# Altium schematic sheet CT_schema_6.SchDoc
size 278 x 170 mm
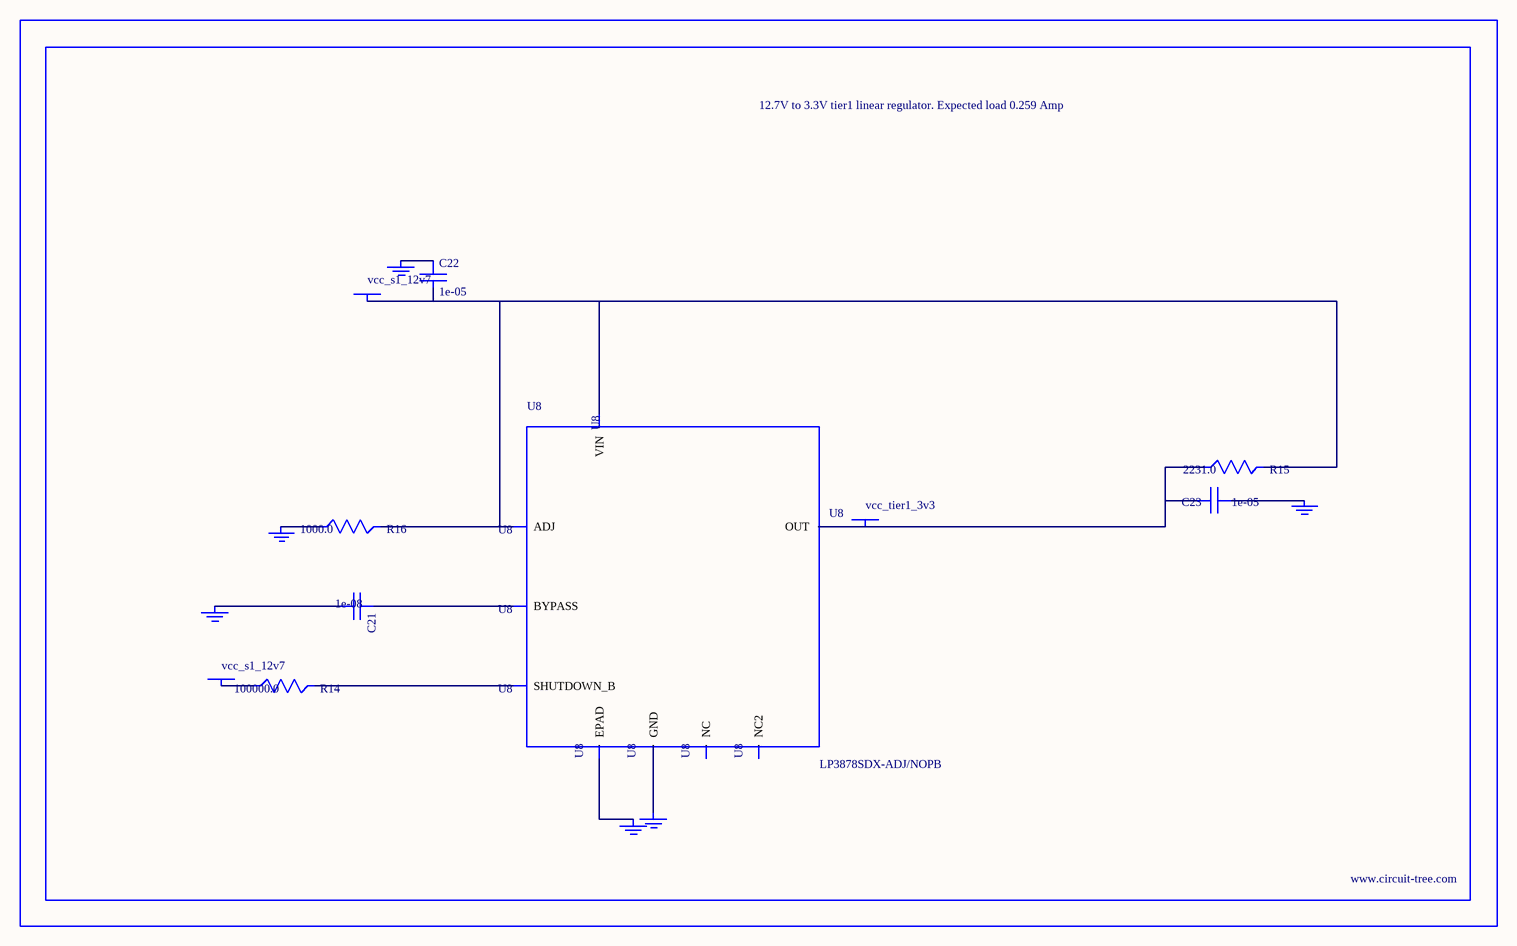
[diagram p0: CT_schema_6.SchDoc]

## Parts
BORDER5  (no value)
C21  1e-08  [C0402]
C22  1e-05  [C1210]
C23  1e-05  [C1210]
GND_INSTANCE_5_0  (no value)
GND_INSTANCE_5_1  (no value)
GND_INSTANCE_5_2  (no value)
GND_INSTANCE_5_3  (no value)
GND_INSTANCE_5_4  (no value)
GND_INSTANCE_5_5  (no value)
POWER_INSTANCE_5_0  vcc_s1_12v7
POWER_INSTANCE_5_1  vcc_s1_12v7
POWER_INSTANCE_5_2  vcc_tier1_3v3
R14  100000.0  [R0603]
R15  2231.0  [R0603]
R16  1000.0  [R0603]
U8  LP3878SDX-ADJ/NOPB  [WSON-8]

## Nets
NetC21_1: C21.1 U8.1(BYPASS)
NetC21_2: C21.2 GND_INSTANCE_5_0.0(GND)
NetC22_1: C22.1 GND_INSTANCE_5_1.0(GND)
NetC22_2: C22.2 POWER_INSTANCE_5_0.0(PWR) R15.2 R16.2 U8.4(VIN) U8.6(ADJ)
NetC23_1: C23.1 GND_INSTANCE_5_2.0(GND)
NetC23_2: C23.2 POWER_INSTANCE_5_2.0(PWR) R15.1 U8.5(OUT)
NetGND_INSTANCE_5_3_0: GND_INSTANCE_5_3.0(GND) R16.1
NetGND_INSTANCE_5_4_0: GND_INSTANCE_5_4.0(GND) U8.PAD(EPAD)
NetGND_INSTANCE_5_5_0: GND_INSTANCE_5_5.0(GND) U8.3(GND)
NetPOWER_INSTANCE_5_1_0: POWER_INSTANCE_5_1.0(PWR) R14.1
NetR14_2: R14.2 U8.8(SHUTDOWN_B)

Not connected (* = marked no-connect by the designer): U8 2(NC) 7(NC2)

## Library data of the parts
BORDER5 = BORDER_PAGE5
C21 = C0402C103K3RAC
C22 = C1210C106K5PACTU
C23 = GRM32DR61E106MA12L
GND_INSTANCE_5_0-GND_INSTANCE_5_5 = GND
POWER_INSTANCE_5_0-POWER_INSTANCE_5_2 = PWR
R14 = RC0603JR-07100KL
R15 = R15
R16 = RC0603JR-071KL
